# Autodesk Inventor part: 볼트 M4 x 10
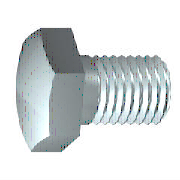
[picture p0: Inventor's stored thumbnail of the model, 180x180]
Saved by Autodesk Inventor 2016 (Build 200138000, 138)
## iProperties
Created: 2012-02
Part Number: 볼트 M4 x 10
Material: 스테인리스강
Description: 6각 머리 나사
Document SubType Name: Modeling
Standard: ISO 4017
Designer: mduedu
Standard Revision: Third edition 1999-08-15
Standards Organization: ISO
Language: ko-KR
Size Designation: M4 x 10
Categories: <MemberInstance><Categories><Category DisplayName="조임쇠" InternalName="e4da775c-781d-43d5-af7c-5136215cf5a6" Mnemonic="FSTN"><Category DisplayName="볼트" InternalN
Density: 8.08 g/cm^3
Appearance: 반광택
IsCustomPart: 0
Author: mduedu
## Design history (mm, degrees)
sketch "스케치1"
  geometry: L1 (0, 3.015)-(0, 2); L2 (2.1, 2)-(10, 2); L3 (10, 2)-(10, 0); L4 (10, 0)-(-0.4, 0); L5 (-2.48, 0)-(12.08, 0) reference; L6 (-0.4, 0)-(-0.4, 3.015); L7 (-0.4, 3.015)-(0, 3.015); L8 (2.1, 2)-(1.67, 2); L9 (1.67, 2)-(0, 2); L10 (0, -0.603)-(0, 3.618) reference
  constraints: 16 end point, 2 collinear, 2 perpendicular, 1 parallel
  dimensions: "d0" = 10 distance between parallel lines of L3 L1 (= NLG); "d1" = 7.9 distance from line of L2.start L3 (= GEL); "d2" = 4 diameter of L2 L4 (= GD); "d9" = 0.4001 distance between parallel lines of L6 L1 (computed from SD); "d10" = 6.03 diameter of L7 L4 (= SD2); "d13" = 0.42952 distance of L2.start L8.end (computed from GAL); "d14" = 4 diameter of L9 L4 (= BDM)
revolve "본체" sketch "스케치1" stored, may be unused: angle "d12" = 90 deg
sketch "스케치2"
  geometry: L1 (0, 4.041)-(3.5, 2.021); L2 (3.5, 2.021)-(3.5, -2.021); L3 (3.5, -2.021)-(0, -4.041); L4 (0, -4.041)-(-3.5, -2.021); L5 (-3.5, -2.021)-(-3.5, 2.021); L6 (-3.5, 2.021)-(0, 4.041); 2 further points
  constraints: 12 end point, 1 coincident, 1 vertical, 11 other
  dimensions: "d11" = 7 distance between parallel lines of L5 L2 (= SW)
extrude "머리" join sketch "스케치2" distance "d3" = 2.4 (= KOH - SD); taper "d4" = 0 deg
sketch "스케치4"
  geometry: L1 (-2.8, 3.5)-(-2.8, 4.041); L2 (-2.8, 4.041)-(-2.487, 4.041); L3 (-2.487, 4.041)-(-2.8, 3.5); L4 (-3.28, 0)-(0.08, 0) reference; L5 (-0.4, 4.041)-(-2.8, 4.041) reference; L6 (-2.8, 2.021)-(-2.8, 4.041) reference
  constraints: 6 end point, 2 collinear, 1 perpendicular, 1 vertical
  dimensions: "d5" = 30 deg angle of L3 L1 (= ANG1); "d19" = 7 diameter of L1.start L4 (= SW0)
revolve "모따기1" sketch "스케치4" stored, may be unused: angle "d21" = 90 deg
workplane "Work Plane1"
body "Solid1"
feature "스레드" dims "d15" = 7.9 (= GEL), "d16" = 0
chamfer "모따기2" distance "d6" = 0.42941 (= -0.5 x SPD + 0.5 x GD); stored, may be unused: second distance "d7" = 0.42952 (computed from GUL), angle "d55" = 45 deg
other parameters: "NLG" = 10 [user parameter; used in 1 equation term], "GD" = 4 (= NND) [user parameter; used in 2 equation terms], "BDM" = 4 (= NND) [user parameter; used in 1 equation term], "KOH" = 2.8 [user parameter; used in 1 equation term], "GEL" = 7.9 [user parameter; used in 2 equation terms], "SW" = 7 [user parameter; used in 2 equation terms], "SW0" = 7 (= SW) [user parameter; used in 1 equation term], "SPD" = 3.14117 (= NND - 1.2269 x PTC) [user parameter; used in 1 equation term], "SD2" = 6.03 [user parameter; used in 2 equation terms], "SD" = 0.4 [user parameter; used in 2 equation terms], "ANG1" = 30 deg [user parameter; used in 1 equation term], "GAL" = 0.42941 (= 0.61345 x PTC) [user parameter; used in 1 equation term], "GUL" = 0.42941 (= 0.61345 x PTC) [user parameter; used in 1 equation term], "d8" = 0, "RR" = 0.2 [user parameter], "d57" = 0, "d58" = 0, "TPU" = 14.28571 (computed from PTC) [user parameter], "GD1" = 3.14117 (= THREADDIA - 1.2269 x PTC) [user parameter], "THREADDIA" = 4 [user parameter; used in 1 equation term], "SDH" = 6.03 (= SD2) [user parameter], "SDHG" = 2.1 [user parameter], "TOA" = 30 deg [user parameter], "PTC" = 0.7 [user parameter; used in 5 equation terms], "NND" = 4 [user parameter; used in 3 equation terms], "E0" = 8.085 [user parameter]
